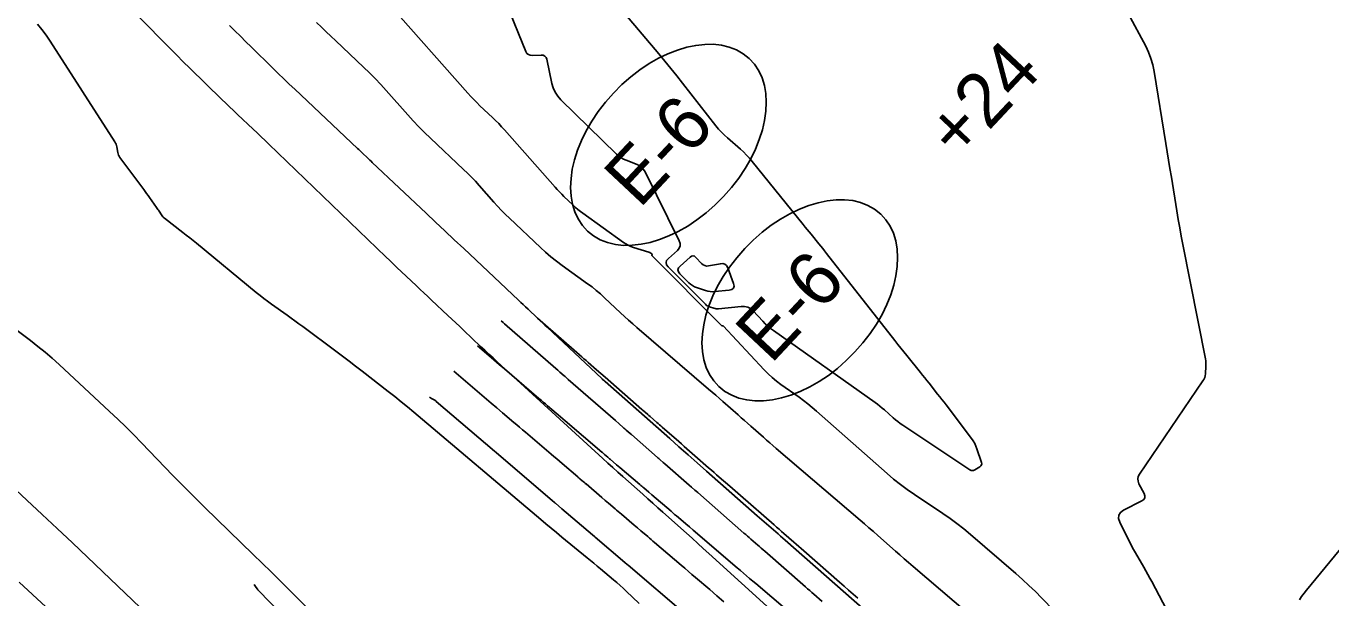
# Model space of a CAD drawing. Extents: x 1005228 to 1008882, y 1883389 to 1885754.
# Drawn here: x 1007015.2 to 1007166.4, y 1885401.9 to 1885468.1 of the extents above; entities that cross this region are included whole.
import ezdxf

# ---------------------------------------------------------------- set-up
doc = ezdxf.new("R2010")
doc.units = 0
for name, color, linetype in [('ATDIMS', 7, 'Continuous'), ('C-ANNO-NOTE', 7, 'Continuous'), ('R_Erosion', 7, 'Continuous'), ('S_BASELINE', 7, 'Continuous'), ('S_BRIDGE', 7, 'Continuous'), ('TSOBSTACLE', 7, 'Continuous')]:
    doc.layers.add(name, color=color, linetype=linetype)

msp = doc.modelspace()

# ---------------------------------------------------------------- linework, layer by layer
at = {"layer": 'ATDIMS'}
msp.add_lwpolyline([(1007070.25, 1885434), (1007070.5, 1885433.79), (1007070.54, 1885433.76), (1007070.58, 1885433.72), (1007070.62, 1885433.69), (1007070.66, 1885433.66), (1007076.58, 1885428.48), (1007076.82, 1885428.27), (1007077.06, 1885428.06), (1007077.55, 1885427.63), (1007077.67, 1885427.53), (1007077.79, 1885427.42), (1007077.91, 1885427.32), (1007078.03, 1885427.21), (1007083.5, 1885422.44), (1007083.93, 1885422.06), (1007084.41, 1885421.64), (1007084.49, 1885421.57), (1007084.58, 1885421.5), (1007084.66, 1885421.43), (1007084.74, 1885421.35), (1007085.21, 1885420.94), (1007085.26, 1885420.9), (1007085.35, 1885420.82), (1007088.39, 1885418.17), (1007088.46, 1885418.1), (1007088.53, 1885418.04), (1007088.6, 1885417.98), (1007088.67, 1885417.92), (1007089.03, 1885417.61), (1007089.24, 1885417.42), (1007092.05, 1885414.96), (1007092.3, 1885414.75), (1007092.7, 1885414.4), (1007092.86, 1885414.26), (1007093.03, 1885414.11), (1007098.39, 1885409.43), (1007098.59, 1885409.25), (1007098.79, 1885409.08), (1007098.99, 1885408.9), (1007099.19, 1885408.73), (1007100, 1885408.02), (1007100.2, 1885407.85), (1007100.4, 1885407.67), (1007100.6, 1885407.5), (1007100.8, 1885407.32), (1007105.53, 1885403.2), (1007105.77, 1885402.98), (1007106.01, 1885402.77), (1007106.25, 1885402.56), (1007106.49, 1885402.35), (1007107.45, 1885401.51)], dxfattribs=at)
at = {"layer": 'C-ANNO-NOTE'}
for points in [[(1007101.9, 1885400.2), (1007094.33, 1885407.07), (1007093.68, 1885407.65), (1007093.04, 1885408.23), (1007092.39, 1885408.82), (1007091.73, 1885409.4), (1007088.98, 1885411.84), (1007088.4, 1885412.36), (1007087.82, 1885412.87), (1007087.24, 1885413.39), (1007086.66, 1885413.91), (1007084.34, 1885415.97), (1007083.76, 1885416.49), (1007083.18, 1885417.01), (1007082.6, 1885417.53), (1007082.03, 1885418.05), (1007069.81, 1885429.24), (1007069.33, 1885429.69), (1007068.84, 1885430.14), (1007068.36, 1885430.59), (1007067.88, 1885431.04), (1007065.92, 1885432.88), (1007065.46, 1885433.32), (1007065, 1885433.75), (1007064.54, 1885434.18), (1007064.08, 1885434.62), (1007062.2, 1885436.39), (1007061.76, 1885436.8), (1007061.31, 1885437.22), (1007060.87, 1885437.63), (1007060.43, 1885438.05), (1007058.66, 1885439.71), (1007058.22, 1885440.13), (1007057.78, 1885440.55), (1007057.34, 1885440.97), (1007056.91, 1885441.39), (1007043.35, 1885454.44), (1007042.9, 1885454.88), (1007042.44, 1885455.31), (1007041.99, 1885455.74), (1007041.53, 1885456.17), (1007039.71, 1885457.89), (1007039.25, 1885458.33), (1007038.8, 1885458.76), (1007038.35, 1885459.19), (1007037.9, 1885459.63), (1007034.19, 1885463.24), (1007033.43, 1885463.99), (1007032.67, 1885464.75), (1007031.91, 1885465.51), (1007031.16, 1885466.27), (1007022.1, 1885475.51)], [(1007084.66, 1885469.44), (1007088.51, 1885464.89), (1007089.21, 1885464.05), (1007089.91, 1885463.21), (1007090.6, 1885462.36), (1007091.28, 1885461.5), (1007095.14, 1885456.58), (1007095.45, 1885456.2), (1007095.78, 1885455.84), (1007096.13, 1885455.49), (1007096.49, 1885455.16), (1007097.98, 1885453.87), (1007098.34, 1885453.54), (1007098.69, 1885453.19), (1007099.02, 1885452.83), (1007099.34, 1885452.45), (1007105.25, 1885445.13), (1007105.48, 1885444.85), (1007105.7, 1885444.57), (1007105.93, 1885444.29), (1007106.16, 1885444.02), (1007107.07, 1885442.91), (1007107.3, 1885442.63), (1007107.52, 1885442.36), (1007107.74, 1885442.08), (1007107.97, 1885441.8), (1007115.87, 1885431.71), (1007116.21, 1885431.27), (1007116.55, 1885430.84), (1007116.9, 1885430.4), (1007117.25, 1885429.97), (1007118.83, 1885428), (1007119.08, 1885427.69), (1007119.33, 1885427.38), (1007119.58, 1885427.07), (1007119.83, 1885426.76), (1007120.83, 1885425.51), (1007121.08, 1885425.2), (1007121.32, 1885424.89), (1007121.57, 1885424.57), (1007121.81, 1885424.26), (1007124.77, 1885420.36), (1007124.96, 1885420.09), (1007125.13, 1885419.8), (1007125.27, 1885419.5), (1007125.39, 1885419.19), (1007125.91, 1885417.61), (1007125.94, 1885417.45), (1007125.92, 1885417.32), (1007125.85, 1885417.2), (1007125.72, 1885417.1), (1007125.13, 1885416.74), (1007124.99, 1885416.67), (1007124.84, 1885416.65), (1007124.7, 1885416.67), (1007124.55, 1885416.75), (1007116.78, 1885421.93), (1007116.5, 1885422.12), (1007116.22, 1885422.33), (1007115.95, 1885422.54), (1007115.69, 1885422.77), (1007114.66, 1885423.68), (1007114.4, 1885423.9), (1007114.13, 1885424.12), (1007113.86, 1885424.33), (1007113.58, 1885424.53), (1007101.81, 1885432.87), (1007101.48, 1885433.12), (1007101.16, 1885433.38), (1007100.86, 1885433.66), (1007100.57, 1885433.95), (1007099.44, 1885435.15), (1007099.15, 1885435.41), (1007098.82, 1885435.58), (1007098.45, 1885435.67), (1007098.06, 1885435.67), (1007095.45, 1885435.39), (1007095.31, 1885435.38), (1007095.18, 1885435.39), (1007095.04, 1885435.41), (1007094.91, 1885435.45), (1007094.38, 1885435.63), (1007094.25, 1885435.68), (1007094.13, 1885435.74), (1007094.02, 1885435.82), (1007093.92, 1885435.91), (1007089.61, 1885440.23), (1007089.42, 1885440.48), (1007089.36, 1885440.73), (1007089.43, 1885440.97), (1007089.63, 1885441.2), (1007090.67, 1885442.14), (1007090.88, 1885442.39), (1007090.99, 1885442.66), (1007090.99, 1885442.94), (1007090.88, 1885443.25), (1007086.93, 1885451.24), (1007086.76, 1885451.52), (1007086.55, 1885451.75), (1007086.3, 1885451.94), (1007086.01, 1885452.09), (1007084.75, 1885452.58), (1007084.45, 1885452.72), (1007084.16, 1885452.88), (1007083.89, 1885453.07), (1007083.64, 1885453.29), (1007077.18, 1885459.59), (1007076.81, 1885460), (1007076.51, 1885460.46), (1007076.29, 1885460.95), (1007076.14, 1885461.48), (1007075.54, 1885464.27), (1007075.46, 1885464.49), (1007075.33, 1885464.65), (1007075.14, 1885464.73), (1007074.91, 1885464.76), (1007073.86, 1885464.71), (1007073.61, 1885464.73), (1007073.41, 1885464.81), (1007073.25, 1885464.96), (1007073.13, 1885465.17), (1007068.73, 1885476.02)], [(1007086.23, 1885401.28), (1007084.76, 1885402.69), (1007084.4, 1885403.03), (1007084.03, 1885403.36), (1007083.66, 1885403.69), (1007083.28, 1885404.01), (1007081.76, 1885405.29), (1007081.38, 1885405.61), (1007081, 1885405.93), (1007080.61, 1885406.24), (1007080.23, 1885406.56), (1007077.29, 1885408.96), (1007076.68, 1885409.47), (1007076.06, 1885409.98), (1007075.45, 1885410.49), (1007074.84, 1885411), (1007060.15, 1885423.41), (1007059.41, 1885424.02), (1007058.67, 1885424.62), (1007057.93, 1885425.22), (1007057.18, 1885425.81), (1007054.16, 1885428.15), (1007053.4, 1885428.74), (1007052.64, 1885429.32), (1007051.88, 1885429.89), (1007051.11, 1885430.47), (1007047.27, 1885433.33), (1007046.82, 1885433.66), (1007046.37, 1885433.99), (1007045.92, 1885434.32), (1007045.47, 1885434.64), (1007043.65, 1885435.93), (1007043.2, 1885436.26), (1007042.76, 1885436.59), (1007042.32, 1885436.93), (1007041.88, 1885437.28), (1007034.94, 1885442.97), (1007034.56, 1885443.29), (1007034.17, 1885443.6), (1007033.78, 1885443.9), (1007033.39, 1885444.21), (1007031.25, 1885445.88), (1007031.15, 1885445.96), (1007031.06, 1885446.05), (1007030.98, 1885446.15), (1007030.9, 1885446.25), (1007030.62, 1885446.68), (1007030.55, 1885446.79), (1007030.48, 1885446.89), (1007030.41, 1885447), (1007030.33, 1885447.1), (1007029.51, 1885448.28), (1007029.34, 1885448.51), (1007029.18, 1885448.74), (1007029.01, 1885448.97), (1007028.84, 1885449.2), (1007026.08, 1885452.92), (1007025.99, 1885453.05), (1007025.92, 1885453.19), (1007025.87, 1885453.34), (1007025.83, 1885453.49), (1007025.73, 1885454.12), (1007025.69, 1885454.28), (1007025.64, 1885454.43), (1007025.58, 1885454.57), (1007025.5, 1885454.71), (1007018.01, 1885466.37), (1007017.54, 1885467.06), (1007017.05, 1885467.72), (1007016.53, 1885468.35)], [(1007038.79, 1885468.17), (1007039.41, 1885467.55), (1007040.04, 1885466.93), (1007040.66, 1885466.31), (1007041.29, 1885465.7), (1007043.81, 1885463.24), (1007044.44, 1885462.63), (1007045.08, 1885462.02), (1007045.71, 1885461.41), (1007046.35, 1885460.81), (1007053.62, 1885453.96), (1007053.76, 1885453.82), (1007053.91, 1885453.69), (1007054.05, 1885453.55), (1007054.19, 1885453.41), (1007054.76, 1885452.87), (1007054.9, 1885452.73), (1007055.04, 1885452.59), (1007055.19, 1885452.46), (1007055.33, 1885452.32), (1007061.57, 1885446.45), (1007062.65, 1885445.43), (1007063.74, 1885444.4), (1007064.83, 1885443.38), (1007065.92, 1885442.36), (1007072.25, 1885436.4), (1007072.53, 1885436.13), (1007072.81, 1885435.87), (1007073.09, 1885435.61), (1007073.37, 1885435.35), (1007074.48, 1885434.3), (1007074.76, 1885434.04), (1007075.04, 1885433.78), (1007075.32, 1885433.51), (1007075.59, 1885433.25), (1007081.92, 1885427.3), (1007081.95, 1885427.27), (1007081.98, 1885427.24), (1007082.02, 1885427.21), (1007082.05, 1885427.18), (1007082.18, 1885427.07), (1007082.22, 1885427.04), (1007082.25, 1885427.01), (1007082.28, 1885426.98), (1007082.32, 1885426.96), (1007089.79, 1885420.36), (1007090.85, 1885419.42), (1007091.92, 1885418.48), (1007092.98, 1885417.54), (1007094.05, 1885416.6), (1007099.91, 1885411.42), (1007100.18, 1885411.19), (1007100.45, 1885410.95), (1007100.72, 1885410.72), (1007100.99, 1885410.48), (1007102.08, 1885409.55), (1007102.36, 1885409.32), (1007102.63, 1885409.08), (1007102.9, 1885408.85), (1007103.17, 1885408.61), (1007116.92, 1885396.53)], [(1007129.08, 1885396.11), (1007117.99, 1885405.57), (1007117.47, 1885406.01), (1007116.96, 1885406.45), (1007116.44, 1885406.9), (1007115.93, 1885407.34), (1007113.89, 1885409.14), (1007113.38, 1885409.59), (1007112.87, 1885410.03), (1007112.35, 1885410.48), (1007111.84, 1885410.92), (1007102.12, 1885419.23), (1007101.75, 1885419.55), (1007101.38, 1885419.87), (1007101.01, 1885420.19), (1007100.64, 1885420.51), (1007099.18, 1885421.81), (1007098.81, 1885422.13), (1007098.44, 1885422.45), (1007098.08, 1885422.78), (1007097.71, 1885423.1), (1007095.95, 1885424.65), (1007095.54, 1885425.02), (1007095.12, 1885425.38), (1007094.7, 1885425.74), (1007094.28, 1885426.1), (1007085.98, 1885433.23), (1007085.5, 1885433.64), (1007085.03, 1885434.07), (1007084.56, 1885434.49), (1007084.09, 1885434.93), (1007082.24, 1885436.67), (1007081.77, 1885437.1), (1007081.28, 1885437.51), (1007080.79, 1885437.91), (1007080.27, 1885438.29), (1007077.32, 1885440.41), (1007076.67, 1885440.89), (1007076.03, 1885441.4), (1007075.41, 1885441.93), (1007074.81, 1885442.48), (1007071.21, 1885445.88), (1007070.75, 1885446.32), (1007070.29, 1885446.78), (1007069.85, 1885447.25), (1007069.42, 1885447.73), (1007067.71, 1885449.67), (1007067.27, 1885450.15), (1007066.83, 1885450.62), (1007066.37, 1885451.08), (1007065.91, 1885451.53), (1007062.07, 1885455.15), (1007061.39, 1885455.81), (1007060.73, 1885456.47), (1007060.08, 1885457.16), (1007059.45, 1885457.85), (1007056.94, 1885460.67), (1007056.31, 1885461.37), (1007055.66, 1885462.05), (1007055, 1885462.72), (1007054.32, 1885463.37), (1007051.09, 1885466.4), (1007050.54, 1885466.93), (1007049.98, 1885467.45), (1007049.43, 1885467.99), (1007048.87, 1885468.52)], [(1007049.98, 1885398.6), (1007045.63, 1885402.93), (1007044.62, 1885403.94), (1007043.6, 1885404.94), (1007042.57, 1885405.95), (1007041.54, 1885406.94), (1007035.93, 1885412.39), (1007034.99, 1885413.3), (1007034.06, 1885414.22), (1007033.15, 1885415.15), (1007032.23, 1885416.09), (1007028.6, 1885419.85), (1007027.69, 1885420.79), (1007026.76, 1885421.71), (1007025.83, 1885422.61), (1007024.87, 1885423.51), (1007019.03, 1885428.93), (1007018.23, 1885429.66), (1007017.41, 1885430.36), (1007016.58, 1885431.04), (1007015.73, 1885431.7), (1007012.3, 1885434.3)], [(1007029.32, 1885399.96), (1007022.33, 1885406.62), (1007020.58, 1885408.28), (1007018.83, 1885409.94), (1007017.07, 1885411.59), (1007015.31, 1885413.24), (1007001.62, 1885426.01)], [(1007170.59, 1885411.33), (1007163.58, 1885402.82), (1007163.28, 1885402.45), (1007163, 1885402.08), (1007162.74, 1885401.7)], [(1007017.49, 1885400.88), (1007015.94, 1885402.31), (1007014.4, 1885403.74)]]:
    msp.add_lwpolyline(points, dxfattribs=at)
msp.add_lwpolyline([(1007092.65, 1885437.94), (1007092.42, 1885438.07), (1007092.2, 1885438.22), (1007091.99, 1885438.4), (1007090.97, 1885439.43), (1007090.8, 1885439.66), (1007090.74, 1885439.89), (1007090.81, 1885440.12), (1007091, 1885440.34), (1007092.14, 1885441.37), (1007092.31, 1885441.49), (1007092.49, 1885441.53), (1007092.66, 1885441.48), (1007092.82, 1885441.34), (1007093.48, 1885440.63), (1007093.66, 1885440.48), (1007093.85, 1885440.38), (1007094.06, 1885440.34), (1007094.29, 1885440.36), (1007095.67, 1885440.6), (1007095.95, 1885440.62), (1007096.19, 1885440.54), (1007096.37, 1885440.38), (1007096.51, 1885440.13), (1007097.17, 1885438.33), (1007097.24, 1885438.02), (1007097.18, 1885437.79), (1007097, 1885437.63), (1007096.69, 1885437.55), (1007095.02, 1885437.38), (1007094.74, 1885437.36), (1007094.48, 1885437.38), (1007094.21, 1885437.42), (1007093.95, 1885437.49), (1007092.9, 1885437.84)], close=True, dxfattribs=at)
at = {"layer": 'R_Erosion'}
for centre in [(1007089.64, 1885454.37), (1007104.86, 1885436.37)]:
    msp.add_ellipse(centre, major_axis=(9.37, 9.99), ratio=0.638788, dxfattribs=at)
at = {"layer": 'S_BRIDGE'}
for points in [[(1007135.75, 1885398.95), (1007132.87, 1885401.93), (1007132.15, 1885402.65), (1007131.41, 1885403.36), (1007130.66, 1885404.05), (1007129.9, 1885404.73), (1007124.62, 1885409.27), (1007123.86, 1885409.91), (1007123.07, 1885410.53), (1007122.27, 1885411.12), (1007121.45, 1885411.68), (1007118.13, 1885413.9), (1007117.31, 1885414.46), (1007116.51, 1885415.06), (1007115.73, 1885415.68), (1007114.97, 1885416.32), (1007106.79, 1885423.55), (1007106.3, 1885423.97), (1007105.8, 1885424.37), (1007105.29, 1885424.77), (1007104.77, 1885425.15), (1007102.67, 1885426.63), (1007102.16, 1885427.02), (1007101.67, 1885427.43), (1007101.2, 1885427.86), (1007100.75, 1885428.32), (1007095.99, 1885433.4), (1007095.98, 1885433.41), (1007095.97, 1885433.41), (1007095.96, 1885433.41), (1007095.95, 1885433.41), (1007095.88, 1885433.41), (1007095.88, 1885433.41), (1007095.88, 1885433.41), (1007095.87, 1885433.41), (1007095.87, 1885433.41), (1007095.86, 1885433.41), (1007095.85, 1885433.41), (1007095.85, 1885433.42), (1007095.85, 1885433.42), (1007095.84, 1885433.42), (1007087.73, 1885441.55), (1007087.72, 1885441.56), (1007087.72, 1885441.57), (1007087.73, 1885441.57), (1007087.73, 1885441.58), (1007087.75, 1885441.6), (1007087.76, 1885441.6), (1007087.76, 1885441.61), (1007087.76, 1885441.62), (1007087.76, 1885441.62), (1007087.69, 1885441.77), (1007087.67, 1885441.79), (1007087.65, 1885441.81), (1007087.63, 1885441.83), (1007087.61, 1885441.84), (1007087.49, 1885441.89), (1007087.46, 1885441.9), (1007087.43, 1885441.91), (1007087.4, 1885441.92), (1007087.38, 1885441.93), (1007085.58, 1885442.5), (1007085.27, 1885442.61), (1007084.98, 1885442.74), (1007084.7, 1885442.9), (1007084.43, 1885443.08), (1007079.74, 1885446.44), (1007079.44, 1885446.66), (1007079.15, 1885446.89), (1007078.88, 1885447.13), (1007078.6, 1885447.38), (1007077.53, 1885448.39), (1007077.27, 1885448.65), (1007077.01, 1885448.91), (1007076.76, 1885449.18), (1007076.51, 1885449.45), (1007070.65, 1885456.09), (1007070.31, 1885456.46), (1007069.97, 1885456.82), (1007069.62, 1885457.18), (1007069.26, 1885457.53), (1007067.8, 1885458.9), (1007067.45, 1885459.25), (1007067.09, 1885459.6), (1007066.75, 1885459.96), (1007066.41, 1885460.33), (1007057.08, 1885470.85)], [(1007142.92, 1885469.58), (1007144.94, 1885465.79), (1007145.28, 1885465.09), (1007145.55, 1885464.36), (1007145.77, 1885463.62), (1007145.93, 1885462.85), (1007147.27, 1885454.54), (1007147.43, 1885453.57), (1007147.59, 1885452.59), (1007147.75, 1885451.61), (1007147.91, 1885450.63), (1007148.55, 1885446.72), (1007148.71, 1885445.74), (1007148.88, 1885444.76), (1007149.06, 1885443.79), (1007149.25, 1885442.82), (1007151.85, 1885429.6), (1007151.89, 1885429.38), (1007151.91, 1885429.17), (1007151.92, 1885428.95), (1007151.91, 1885428.73), (1007151.85, 1885427.84), (1007151.82, 1885427.63), (1007151.77, 1885427.42), (1007151.68, 1885427.22), (1007151.57, 1885427.04), (1007144.22, 1885416.23), (1007144.08, 1885415.97), (1007144.03, 1885415.7), (1007144.05, 1885415.42), (1007144.16, 1885415.14), (1007144.76, 1885414.02), (1007144.85, 1885413.75), (1007144.84, 1885413.52), (1007144.72, 1885413.32), (1007144.49, 1885413.16), (1007142.38, 1885412.06), (1007142.02, 1885411.81), (1007141.82, 1885411.49), (1007141.79, 1885411.12), (1007141.93, 1885410.7), (1007142.87, 1885408.8), (1007143.08, 1885408.37), (1007143.3, 1885407.95), (1007143.53, 1885407.53), (1007143.76, 1885407.12), (1007144.71, 1885405.47), (1007144.94, 1885405.05), (1007145.17, 1885404.64), (1007145.4, 1885404.22), (1007145.63, 1885403.8), (1007147.77, 1885399.77)]]:
    msp.add_lwpolyline(points, dxfattribs=at)
at = {"layer": 'TSOBSTACLE'}
for points in [[(1007074.78, 1885434.03), (1007079.35, 1885430.04), (1007079.6, 1885429.83), (1007079.84, 1885429.61), (1007080.09, 1885429.4), (1007080.34, 1885429.18), (1007081.32, 1885428.32), (1007081.82, 1885427.89), (1007082.31, 1885427.46), (1007086.56, 1885423.74), (1007086.63, 1885423.69), (1007086.69, 1885423.63), (1007086.82, 1885423.52), (1007086.88, 1885423.47), (1007086.94, 1885423.41), (1007087.26, 1885423.14), (1007087.38, 1885423.03), (1007087.51, 1885422.92), (1007088.31, 1885422.22), (1007088.46, 1885422.09), (1007088.61, 1885421.95), (1007088.77, 1885421.82), (1007088.92, 1885421.68), (1007090.84, 1885420.01), (1007091.15, 1885419.74), (1007091.46, 1885419.46), (1007092.08, 1885418.92), (1007092.4, 1885418.65), (1007092.71, 1885418.37), (1007094.3, 1885416.98), (1007094.61, 1885416.71), (1007094.92, 1885416.44), (1007095.22, 1885416.18), (1007095.53, 1885415.91), (1007096.75, 1885414.84), (1007097.06, 1885414.57), (1007097.37, 1885414.3), (1007097.67, 1885414.03), (1007097.98, 1885413.77), (1007101.88, 1885410.36), (1007102.17, 1885410.11), (1007102.45, 1885409.86), (1007102.74, 1885409.61), (1007103.02, 1885409.36), (1007104.16, 1885408.37), (1007104.45, 1885408.12), (1007104.74, 1885407.87), (1007105.02, 1885407.62), (1007105.31, 1885407.37), (1007109.46, 1885403.74), (1007109.99, 1885403.28), (1007110.52, 1885402.81), (1007111.58, 1885401.88)], [(1007105.31, 1885398.84), (1007099.76, 1885403.57), (1007099.41, 1885403.87), (1007099.05, 1885404.18), (1007097.98, 1885405.09), (1007097.62, 1885405.4), (1007092.5, 1885409.77), (1007092.07, 1885410.13), (1007091.65, 1885410.5), (1007090.79, 1885411.23), (1007090.58, 1885411.41), (1007090.36, 1885411.59), (1007090.15, 1885411.77), (1007089.94, 1885411.95), (1007087.72, 1885413.84), (1007087.37, 1885414.14), (1007086.79, 1885414.64), (1007086.67, 1885414.74), (1007086.56, 1885414.84), (1007086.44, 1885414.94), (1007086.33, 1885415.04), (1007084, 1885417.02), (1007083.62, 1885417.34), (1007082.89, 1885417.97), (1007082.82, 1885418.03), (1007082.75, 1885418.09), (1007082.68, 1885418.15), (1007082.61, 1885418.21), (1007082.24, 1885418.52), (1007082.14, 1885418.61), (1007082.04, 1885418.7), (1007081.99, 1885418.74), (1007081.94, 1885418.78), (1007077.66, 1885422.43), (1007077.15, 1885422.86), (1007076.65, 1885423.29), (1007075.64, 1885424.15), (1007075.39, 1885424.37), (1007075.13, 1885424.58), (1007074.88, 1885424.8), (1007074.63, 1885425.02), (1007070.64, 1885428.42), (1007070.01, 1885428.95), (1007069.39, 1885429.49), (1007067.52, 1885431.08)], [(1007096.07, 1885401.47), (1007095.24, 1885402.17), (1007094.42, 1885402.88), (1007092.77, 1885404.28), (1007092.36, 1885404.64), (1007091.95, 1885404.99), (1007091.53, 1885405.34), (1007091.12, 1885405.69), (1007088.02, 1885408.34), (1007087.82, 1885408.5), (1007087.63, 1885408.67), (1007087.43, 1885408.84), (1007087.24, 1885409.01), (1007086.45, 1885409.67), (1007086.06, 1885410.01), (1007085.67, 1885410.34), (1007084.2, 1885411.6), (1007084.01, 1885411.76), (1007083.82, 1885411.92), (1007083.63, 1885412.08), (1007083.45, 1885412.24), (1007082.69, 1885412.89), (1007082.31, 1885413.21), (1007081.94, 1885413.53), (1007080.09, 1885415.11), (1007080.05, 1885415.14), (1007080.01, 1885415.17), (1007079.98, 1885415.2), (1007079.94, 1885415.23), (1007079.76, 1885415.39), (1007079.64, 1885415.48), (1007079.37, 1885415.72), (1007079.31, 1885415.77), (1007079.25, 1885415.82), (1007079.19, 1885415.87), (1007079.14, 1885415.92), (1007077.34, 1885417.46), (1007077.02, 1885417.73), (1007076.7, 1885418), (1007076.38, 1885418.27), (1007076.06, 1885418.55), (1007073.06, 1885421.1), (1007072.73, 1885421.39), (1007072.4, 1885421.67), (1007072.07, 1885421.95), (1007071.74, 1885422.23), (1007070.42, 1885423.35), (1007069.76, 1885423.92), (1007069.1, 1885424.48), (1007064.78, 1885428.16)], [(1007061.97, 1885425.17), (1007062.2, 1885425.02), (1007062.5, 1885424.83), (1007062.56, 1885424.8), (1007062.61, 1885424.76), (1007062.67, 1885424.72), (1007062.72, 1885424.67), (1007069.49, 1885418.9), (1007069.66, 1885418.75), (1007069.7, 1885418.72), (1007076.17, 1885413.2), (1007076.45, 1885412.96), (1007076.48, 1885412.93), (1007076.52, 1885412.9), (1007076.55, 1885412.87), (1007076.59, 1885412.84), (1007077.24, 1885412.28), (1007077.29, 1885412.24), (1007080.85, 1885409.21), (1007081.06, 1885409.03), (1007081.14, 1885408.96), (1007084.57, 1885406.03), (1007084.86, 1885405.78), (1007084.96, 1885405.7), (1007091.65, 1885399.99)], [(1007041.63, 1885403.46), (1007041.79, 1885403.25), (1007042, 1885402.96), (1007042.04, 1885402.91), (1007042.08, 1885402.85), (1007042.12, 1885402.8), (1007042.17, 1885402.75), (1007048.37, 1885396.37)]]:
    msp.add_lwpolyline(points, dxfattribs=at)

# ---------------------------------------------------------------- texts
at = {"layer": 'R_Erosion'}
for p in [(1007086.28, 1885446.89), (1007101.5, 1885428.88)]:
    msp.add_text('E-6', height=6.25, rotation=46.8499, dxfattribs=at).set_placement(p)
at = {"layer": 'S_BASELINE'}
msp.add_text('+24', height=6.25, rotation=46.8499, dxfattribs=at).set_placement((1007123.37, 1885452.34))

doc.saveas('drawing.dxf')
